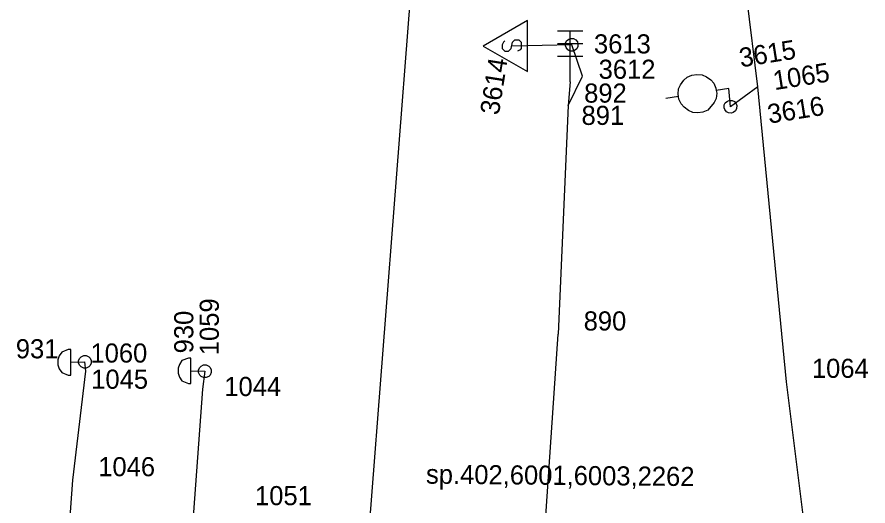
# Model space of a CAD drawing. Extents: x -535557 to -534097, y -1142175 to -1136716.
# Drawn here: x -534404.35 to -534370.94, y -1140158.35 to -1140139.16 of the extents above; entities that cross this region are included whole.
import ezdxf

# ---------------------------------------------------------------- set-up
doc = ezdxf.new("R2010")
doc.units = 0
doc.layers.add('Default', color=7, linetype='Continuous')
doc.layers.add('SS_SZDC', color=7, linetype='Continuous')

# ---------------------------------------------------------------- blocks, each defined once
blk = doc.blocks.new('POINT_DISPLAY')
at = {"layer": 'Default'}
blk.add_line((0, 0), (0, 0), dxfattribs=at)

msp = doc.modelspace()

# ---------------------------------------------------------------- linework, layer by layer
at = {"layer": 'SS_SZDC'}
for p, q in [((-534390.55, -1140159.639), (-534387.529, -1140120.67)), ((-534375.26, -1140141.899), (-534377.1, -1140127.12)), ((-534384.299, -1140139.299), (-534386.049, -1140140.299)), ((-534384.299, -1140141.299), (-534384.299, -1140139.299)), ((-534383.13, -1140139.7), (-534382.13, -1140139.7)), ((-534382.63, -1140141.7), (-534382.63, -1140139.7)), ((-534385.199, -1140140.099), (-534385.249, -1140140.149)), ((-534384.899, -1140140.149), (-534384.799, -1140140.049)), ((-534384.799, -1140140.049), (-534384.649, -1140140.049)), ((-534384.649, -1140140.049), (-534384.549, -1140140.149)), ((-534382.815, -1140140.181), (-534382.77, -1140140.091)), ((-534382.77, -1140140.091), (-534382.68, -1140140.025)), ((-534382.68, -1140140.025), (-534382.612, -1140140.003)), ((-534382.612, -1140140.003), (-534382.501, -1140140.004)), ((-534382.501, -1140140.004), (-534382.411, -1140140.049)), ((-534382.411, -1140140.049), (-534382.345, -1140140.139)), ((-534386.049, -1140140.299), (-534384.299, -1140141.299)), ((-534385.249, -1140140.149), (-534385.299, -1140140.249)), ((-534385.299, -1140140.249), (-534385.299, -1140140.399)), ((-534385.299, -1140140.399), (-534385.199, -1140140.499)), ((-534385.049, -1140140.499), (-534384.949, -1140140.399)), ((-534384.949, -1140140.399), (-534384.899, -1140140.149)), ((-534382.569, -1140140.25), (-534384.899, -1140140.299)), ((-534384.599, -1140140.449), (-534384.699, -1140140.499)), ((-534384.549, -1140140.399), (-534384.599, -1140140.449)), ((-534384.549, -1140140.149), (-534384.549, -1140140.399)), ((-534383.13, -1140140.2), (-534382.13, -1140140.2)), ((-534382.816, -1140140.292), (-534382.815, -1140140.181)), ((-534382.794, -1140140.36), (-534382.816, -1140140.292)), ((-534382.728, -1140140.45), (-534382.794, -1140140.36)), ((-534382.638, -1140140.495), (-534382.728, -1140140.45)), ((-534382.149, -1140141.479), (-534382.569, -1140140.25)), ((-534382.369, -1140140.408), (-534382.459, -1140140.474)), ((-534382.324, -1140140.318), (-534382.369, -1140140.408)), ((-534382.345, -1140140.139), (-534382.323, -1140140.207)), ((-534382.323, -1140140.207), (-534382.324, -1140140.318)), ((-534385.199, -1140140.499), (-534385.049, -1140140.499)), ((-534383.13, -1140140.7), (-534382.13, -1140140.7)), ((-534382.527, -1140140.496), (-534382.638, -1140140.495)), ((-534382.459, -1140140.474), (-534382.527, -1140140.496)), ((-534378.04, -1140141.521), (-534377.85, -1140141.44)), ((-534377.85, -1140141.44), (-534377.653, -1140141.409)), ((-534377.653, -1140141.409), (-534377.447, -1140141.427)), ((-534377.447, -1140141.427), (-534377.284, -1140141.502)), ((-534382.71, -1140142.629), (-534382.149, -1140141.479)), ((-534382.63, -1140141.7), (-534382.71, -1140142.629)), ((-534378.297, -1140141.814), (-534378.172, -1140141.643)), ((-534378.172, -1140141.643), (-534378.04, -1140141.521)), ((-534377.284, -1140141.502), (-534377.112, -1140141.627)), ((-534377.112, -1140141.627), (-534376.99, -1140141.759)), ((-534376.99, -1140141.759), (-534376.909, -1140141.949)), ((-534378.391, -1140142.184), (-534378.372, -1140141.978)), ((-534378.372, -1140141.978), (-534378.297, -1140141.814)), ((-534376.909, -1140141.949), (-534376.893, -1140142.048)), ((-534376.399, -1140141.969), (-534376.893, -1140142.048)), ((-534376.893, -1140142.048), (-534376.878, -1140142.146)), ((-534376.34, -1140142.68), (-534376.399, -1140141.969)), ((-534375.26, -1140141.899), (-534376.34, -1140142.68)), ((-534374.14, -1140153.469), (-534375.26, -1140141.899)), ((-534378.375, -1140142.282), (-534378.869, -1140142.361)), ((-534378.359, -1140142.381), (-534378.391, -1140142.184)), ((-534378.279, -1140142.571), (-534378.359, -1140142.381)), ((-534376.896, -1140142.352), (-534376.971, -1140142.516)), ((-534376.878, -1140142.146), (-534376.896, -1140142.352)), ((-534376.54, -1140142.521), (-534376.45, -1140142.455)), ((-534376.45, -1140142.455), (-534376.382, -1140142.433)), ((-534376.382, -1140142.433), (-534376.271, -1140142.434)), ((-534376.271, -1140142.434), (-534376.181, -1140142.479)), ((-534382.71, -1140142.629), (-534383.1, -1140151.61)), ((-534378.156, -1140142.703), (-534378.279, -1140142.571)), ((-534377.985, -1140142.828), (-534378.156, -1140142.703)), ((-534376.971, -1140142.516), (-534377.228, -1140142.809)), ((-534376.586, -1140142.722), (-534376.585, -1140142.611)), ((-534376.564, -1140142.79), (-534376.586, -1140142.722)), ((-534376.585, -1140142.611), (-534376.54, -1140142.521)), ((-534376.498, -1140142.88), (-534376.564, -1140142.79)), ((-534376.181, -1140142.479), (-534376.115, -1140142.569)), ((-534376.094, -1140142.748), (-534376.139, -1140142.838)), ((-534376.115, -1140142.569), (-534376.093, -1140142.637)), ((-534376.093, -1140142.637), (-534376.094, -1140142.748)), ((-534377.821, -1140142.903), (-534377.985, -1140142.828)), ((-534377.616, -1140142.921), (-534377.821, -1140142.903)), ((-534377.418, -1140142.89), (-534377.616, -1140142.921)), ((-534377.228, -1140142.809), (-534377.418, -1140142.89)), ((-534376.408, -1140142.925), (-534376.498, -1140142.88)), ((-534376.297, -1140142.926), (-534376.408, -1140142.925)), ((-534376.229, -1140142.904), (-534376.297, -1140142.926)), ((-534376.139, -1140142.838), (-534376.229, -1140142.904)), ((-534383.75, -1140161.26), (-534383.1, -1140151.61)), ((-534402.689, -1140152.459), (-534402.739, -1140152.609)), ((-534402.589, -1140152.309), (-534402.689, -1140152.459)), ((-534402.339, -1140152.209), (-534402.589, -1140152.309)), ((-534402.239, -1140152.209), (-534402.339, -1140152.209)), ((-534402.239, -1140153.209), (-534402.239, -1140152.209)), ((-534401.83, -1140152.49), (-534401.73, -1140152.44)), ((-534401.73, -1140152.44), (-534401.63, -1140152.44)), ((-534401.63, -1140152.44), (-534401.53, -1140152.49)), ((-534402.739, -1140152.609), (-534402.739, -1140152.809)), ((-534402.739, -1140152.809), (-534402.689, -1140152.959)), ((-534402.239, -1140152.709), (-534401.68, -1140152.69)), ((-534401.93, -1140152.64), (-534401.88, -1140152.54)), ((-534401.93, -1140152.74), (-534401.93, -1140152.64)), ((-534401.88, -1140152.84), (-534401.93, -1140152.74)), ((-534401.88, -1140152.54), (-534401.83, -1140152.49)), ((-534401.64, -1140153.059), (-534401.68, -1140152.69)), ((-534401.53, -1140152.49), (-534401.48, -1140152.54)), ((-534401.48, -1140152.54), (-534401.43, -1140152.64)), ((-534401.43, -1140152.74), (-534401.48, -1140152.84)), ((-534401.43, -1140152.64), (-534401.43, -1140152.74)), ((-534397.97, -1140152.79), (-534398.02, -1140152.94)), ((-534397.87, -1140152.64), (-534397.97, -1140152.79)), ((-534397.62, -1140152.54), (-534397.87, -1140152.64)), ((-534397.52, -1140152.54), (-534397.62, -1140152.54)), ((-534397.52, -1140153.54), (-534397.52, -1140152.54)), ((-534397.12, -1140152.859), (-534397.02, -1140152.809)), ((-534397.02, -1140152.809), (-534396.92, -1140152.809)), ((-534396.92, -1140152.809), (-534396.82, -1140152.859)), ((-534402.689, -1140152.959), (-534402.589, -1140153.109)), ((-534402.589, -1140153.109), (-534402.339, -1140153.209)), ((-534402.159, -1140157.329), (-534401.64, -1140153.059)), ((-534401.83, -1140152.89), (-534401.88, -1140152.84)), ((-534401.73, -1140152.94), (-534401.83, -1140152.89)), ((-534401.63, -1140152.94), (-534401.73, -1140152.94)), ((-534401.53, -1140152.89), (-534401.63, -1140152.94)), ((-534401.48, -1140152.84), (-534401.53, -1140152.89)), ((-534398.02, -1140152.94), (-534398.02, -1140153.14)), ((-534398.02, -1140153.14), (-534397.97, -1140153.29)), ((-534397.52, -1140153.04), (-534396.97, -1140153.059)), ((-534397.22, -1140153.009), (-534397.17, -1140152.909)), ((-534397.22, -1140153.109), (-534397.22, -1140153.009)), ((-534397.17, -1140153.209), (-534397.22, -1140153.109)), ((-534397.17, -1140152.909), (-534397.12, -1140152.859)), ((-534396.97, -1140153.059), (-534397.069, -1140153.76)), ((-534396.82, -1140152.859), (-534396.77, -1140152.909)), ((-534396.77, -1140152.909), (-534396.72, -1140153.009)), ((-534396.72, -1140153.109), (-534396.77, -1140153.209)), ((-534396.72, -1140153.009), (-534396.72, -1140153.109)), ((-534402.339, -1140153.209), (-534402.239, -1140153.209)), ((-534397.97, -1140153.29), (-534397.87, -1140153.44)), ((-534397.87, -1140153.44), (-534397.62, -1140153.54)), ((-534397.12, -1140153.259), (-534397.17, -1140153.209)), ((-534397.02, -1140153.309), (-534397.12, -1140153.259)), ((-534396.92, -1140153.309), (-534397.02, -1140153.309)), ((-534396.82, -1140153.259), (-534396.92, -1140153.309)), ((-534396.77, -1140153.209), (-534396.82, -1140153.259)), ((-534372.22, -1140168.68), (-534374.14, -1140153.469)), ((-534397.069, -1140153.76), (-534397.63, -1140161.469)), ((-534397.62, -1140153.54), (-534397.52, -1140153.54)), ((-534402.42, -1140161.04), (-534402.159, -1140157.329))]:
    msp.add_line(p, q, dxfattribs=at)

# ---------------------------------------------------------------- block references
for p in [(-534384.899, -1140140.299), (-534382.569, -1140140.25), (-534382.569, -1140140.25), (-534382.63, -1140141.7), (-534382.149, -1140141.479), (-534376.399, -1140141.969), (-534375.26, -1140141.899), (-534382.71, -1140142.629), (-534376.34, -1140142.68), (-534376.34, -1140142.68), (-534383.1, -1140151.61), (-534402.239, -1140152.709), (-534401.68, -1140152.69), (-534401.68, -1140152.69), (-534401.64, -1140153.059), (-534397.52, -1140153.04), (-534396.97, -1140153.059), (-534396.97, -1140153.059), (-534374.14, -1140153.469), (-534397.069, -1140153.76), (-534402.159, -1140157.329)]:
    msp.add_blockref('POINT_DISPLAY', p, dxfattribs=at)

# ---------------------------------------------------------------- texts
for s, p in [('3613', (-534381.696, -1140140.588)), ('3612', (-534381.513, -1140141.584)), ('892', (-534382.082, -1140142.519)), ('891', (-534382.184, -1140143.393)), ('890', (-534382.1, -1140151.46)), ('931', (-534404.394, -1140152.552)), ('1060', (-534401.464, -1140152.719)), ('1064', (-534373.14, -1140153.319)), ('1045', (-534401.434, -1140153.746)), ('1044', (-534396.209, -1140154.032)), ('1046', (-534401.159, -1140157.179)), ('1051', (-534395.003, -1140158.315))]:
    msp.add_text(s, height=0.75, dxfattribs=at).set_placement(p)
for s, height, rotation, p in [('3615', 0.75, 9, (-534375.931, -1140141.137)), ('3614', 0.75, 81, (-534385.433, -1140143.032)), ('1065', 0.75, 9, (-534374.604, -1140142.031)), ('3616', 0.75, 9, (-534374.821, -1140143.345)), ('1059', 0.75, 90, (-534396.424, -1140152.43)), ('930', 0.75, 90, (-534397.426, -1140152.358)), ('sp.402,6001,6003,2262', 0.74999, 359.4757, (-534388.293, -1140157.47))]:
    msp.add_text(s, height=height, rotation=rotation, dxfattribs=at).set_placement(p)

doc.saveas('drawing.dxf')
